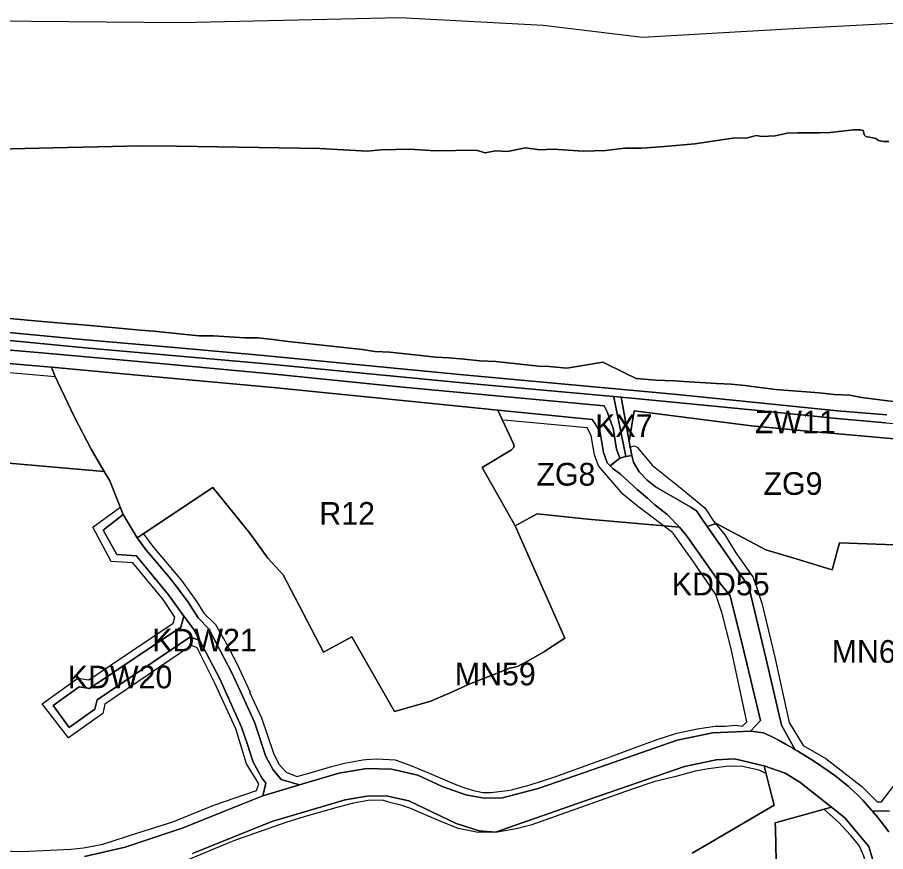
# Model space of a CAD drawing. Extents: x 7428841 to 7433518, y 5545054 to 5546840.
# Drawn here: x 7432847.6 to 7433230.3, y 5546084.6 to 5546452.4 of the extents above; entities that cross this region are included whole.
import ezdxf

# ---------------------------------------------------------------- set-up
doc = ezdxf.new("R2010")
doc.units = 0
for name, color, linetype in [('linie_rozgraniczajace', 7, 'Continuous'), ('linie_zabudowy_nieprzekraczalne', 7, 'Continuous'), ('oznaczenia_przeznaczen', 7, 'Continuous')]:
    doc.layers.add(name, color=color, linetype=linetype)

msp = doc.modelspace()

# ---------------------------------------------------------------- linework, layer by layer
at = {"layer": 'linie_rozgraniczajace'}
for points in [[(7432820.67, 5546451.02), (7432919.88, 5546450.2), (7433016.26, 5546452.41), (7433079.45, 5546449.02), (7433123.15, 5546443.63), (7433164.03, 5546445.99), (7433192.29, 5546447.64), (7433261.86, 5546451.37)], [(7432839.38, 5546394.28), (7432850.87, 5546394.57), (7432869.68, 5546395.04), (7432889.49, 5546395.53), (7432901.99, 5546395.84), (7432917.75, 5546395.6), (7432953.9, 5546395.05), (7432980.95, 5546394.64), (7433001.88, 5546393.38), (7433007.91, 5546394.05), (7433020.66, 5546394.36), (7433031.79, 5546393.58), (7433049.82, 5546393.92), (7433053.75, 5546392.67), (7433058.4, 5546393.58), (7433063.61, 5546393.29), (7433071.62, 5546394.84), (7433077.92, 5546394.01), (7433083.76, 5546394.25), (7433090.41, 5546393.83), (7433097.06, 5546393.42), (7433101.99, 5546393.58), (7433106.92, 5546393.75), (7433115.46, 5546394.81), (7433122.89, 5546394.68), (7433132.88, 5546395.52), (7433146.3, 5546396.65), (7433155.13, 5546397.98), (7433163.95, 5546399.31), (7433168.93, 5546399.15), (7433173.35, 5546400.34), (7433175.83, 5546399.86), (7433178.74, 5546400.05), (7433181.65, 5546400.24), (7433186.87, 5546401.39), (7433191.63, 5546401.44), (7433196.38, 5546401.49), (7433201.14, 5546401.54), (7433205.9, 5546401.58), (7433210.99, 5546402.19), (7433216.09, 5546402.79), (7433217.69, 5546402.78), (7433219.3, 5546402.78), (7433220.4, 5546402.49), (7433220.79, 5546401.54), (7433220.85, 5546400.55), (7433221.64, 5546399.87), (7433223.99, 5546399.38), (7433225.98, 5546398.96), (7433227.25, 5546398.19), (7433229.37, 5546397.75), (7433231.77, 5546397.67)], [(7433231.77, 5546397.67), (7433229.37, 5546397.75), (7433227.25, 5546398.19), (7433225.98, 5546398.96), (7433223.99, 5546399.38), (7433221.64, 5546399.87), (7433220.85, 5546400.55), (7433220.79, 5546401.54), (7433220.4, 5546402.49), (7433219.3, 5546402.78), (7433217.69, 5546402.78), (7433216.09, 5546402.79), (7433210.99, 5546402.19), (7433205.9, 5546401.58), (7433201.14, 5546401.54), (7433196.38, 5546401.49), (7433191.63, 5546401.44), (7433186.87, 5546401.39), (7433181.65, 5546400.24), (7433178.74, 5546400.05), (7433175.83, 5546399.86), (7433173.35, 5546400.34), (7433168.93, 5546399.15), (7433163.95, 5546399.31), (7433155.13, 5546397.98), (7433146.3, 5546396.65), (7433132.88, 5546395.52), (7433122.89, 5546394.68)], [(7433122.89, 5546394.68), (7433115.46, 5546394.81), (7433106.92, 5546393.75), (7433101.99, 5546393.58), (7433097.06, 5546393.42), (7433090.41, 5546393.83), (7433083.76, 5546394.25), (7433077.92, 5546394.01), (7433071.62, 5546394.84), (7433063.61, 5546393.29), (7433058.4, 5546393.58), (7433053.75, 5546392.67), (7433049.82, 5546393.92), (7433031.79, 5546393.58), (7433020.66, 5546394.36), (7433007.91, 5546394.05), (7433001.88, 5546393.38), (7432980.95, 5546394.64), (7432953.9, 5546395.05), (7432917.75, 5546395.6), (7432901.99, 5546395.84), (7432889.49, 5546395.53), (7432869.68, 5546395.04), (7432850.87, 5546394.57), (7432839.38, 5546394.28)], [(7432914.89, 5546313.38), (7432907.84, 5546314.09), (7432901.69, 5546314.57), (7432895.53, 5546315.05), (7432881.27, 5546316.48), (7432874.59, 5546317.01), (7432868.8, 5546317.51), (7432853.66, 5546318.81), (7432842.75, 5546319.75)], [(7432842.75, 5546319.75), (7432853.66, 5546318.81), (7432868.8, 5546317.51), (7432874.59, 5546317.01), (7432881.27, 5546316.48), (7432895.53, 5546315.05), (7432901.69, 5546314.57), (7432907.84, 5546314.09), (7432914.89, 5546313.38), (7432921.93, 5546312.66), (7432927.81, 5546312.07), (7432934.09, 5546312.05), (7432940.99, 5546311.6), (7432947.89, 5546311.16), (7432953.61, 5546311.13), (7432960.28, 5546310.34), (7432967.03, 5546309.58), (7432973.79, 5546308.83), (7432986.14, 5546307.48), (7432999.63, 5546305.92), (7433005.19, 5546305.15), (7433011.86, 5546304.77), (7433018.66, 5546304.05), (7433025.47, 5546303.34), (7433032.01, 5546302.61), (7433037.81, 5546302.29), (7433044.63, 5546301.65), (7433051.45, 5546301.01), (7433058.56, 5546300.64), (7433063.88, 5546300.13), (7433077.52, 5546298.69), (7433082.06, 5546298.54), (7433089.89, 5546297.8), (7433097.78, 5546299.07), (7433105.68, 5546300.35), (7433115.89, 5546295.37), (7433120.39, 5546293.13), (7433129.06, 5546292.49), (7433132.98, 5546292.36), (7433137.28, 5546292.11), (7433141.57, 5546291.86)], [(7433230.83, 5546277.11), (7433209.16, 5546279), (7433173.06, 5546282.65), (7433136.97, 5546286.3), (7433090.54, 5546290.56), (7433044.1, 5546294.82), (7433000.08, 5546299.08), (7432956.05, 5546303.33), (7432916.93, 5546306.79), (7432877.8, 5546310.25), (7432808.08, 5546316.9)], [(7432808.08, 5546316.9), (7432877.8, 5546310.25), (7432916.93, 5546306.79), (7432956.05, 5546303.33), (7433000.08, 5546299.08), (7433044.1, 5546294.82), (7433090.54, 5546290.56), (7433136.97, 5546286.3), (7433173.06, 5546282.65), (7433209.16, 5546279), (7433230.83, 5546277.11)], [(7432807.79, 5546313.42), (7432877.5, 5546306.77), (7432955.75, 5546299.84), (7432999.77, 5546295.59), (7433043.79, 5546291.34), (7433110.39, 5546285.23), (7433110.44, 5546285.12), (7433110.52, 5546284.96), (7433113.18, 5546271.96), (7433115.88, 5546258.74), (7433113.22, 5546258.1), (7433111.76, 5546262.08), (7433110.21, 5546271.36), (7433108.51, 5546275.97), (7433107.78, 5546278.2), (7433106.3, 5546281.18), (7433017.57, 5546289.41), (7432961.02, 5546295.15), (7432902.7, 5546300.48), (7432859.86, 5546304.41), (7432799.1, 5546309.67)], [(7433230.5, 5546273.63), (7433208.84, 5546275.52), (7433172.74, 5546279.17), (7433136.65, 5546282.81), (7433113.77, 5546284.91), (7433110.39, 5546285.23), (7433043.79, 5546291.34), (7432999.77, 5546295.59), (7432955.75, 5546299.84), (7432877.5, 5546306.77), (7432807.79, 5546313.42)], [(7433233.67, 5546283.05), (7433219.69, 5546284.79), (7433214.51, 5546285.82), (7433207.65, 5546286.2), (7433200.99, 5546286.81), (7433181.84, 5546288.37), (7433168.25, 5546290.14), (7433162.28, 5546290.71), (7433155.84, 5546291.02), (7433141.57, 5546291.86), (7433137.28, 5546292.11), (7433132.98, 5546292.36), (7433129.06, 5546292.49), (7433120.39, 5546293.13), (7433115.89, 5546295.37), (7433105.68, 5546300.35), (7433097.78, 5546299.07), (7433089.89, 5546297.8), (7433082.06, 5546298.54), (7433077.52, 5546298.69), (7433063.88, 5546300.13), (7433058.56, 5546300.64), (7433051.45, 5546301.01), (7433044.63, 5546301.65), (7433037.81, 5546302.29), (7433032.01, 5546302.61), (7433025.47, 5546303.34), (7433018.66, 5546304.05), (7433011.86, 5546304.77), (7433005.19, 5546305.15), (7432999.63, 5546305.92), (7432986.14, 5546307.48), (7432973.79, 5546308.83), (7432967.03, 5546309.58), (7432960.28, 5546310.34), (7432953.61, 5546311.13), (7432947.89, 5546311.16), (7432940.99, 5546311.6), (7432934.09, 5546312.05), (7432927.81, 5546312.07), (7432921.93, 5546312.66), (7432914.89, 5546313.38)], [(7432799.1, 5546309.67), (7432859.86, 5546304.41), (7432902.7, 5546300.48), (7432961.02, 5546295.15), (7433017.57, 5546289.41), (7433106.3, 5546281.18), (7433107.78, 5546278.2), (7433108.51, 5546275.97), (7433110.21, 5546271.36), (7433111.76, 5546262.08), (7433113.22, 5546258.1), (7433108.92, 5546254.68), (7433107.59, 5546256.03), (7433105.93, 5546260.53), (7433104.45, 5546269.39), (7433102.36, 5546273.27), (7433100.96, 5546275.11), (7433072.74, 5546277.92), (7433059.45, 5546279.24), (7433027.71, 5546282.4), (7432960.43, 5546289.18), (7432902.15, 5546294.5), (7432862.64, 5546298.13), (7432859.33, 5546298.44), (7432798.57, 5546303.7)], [(7432798.57, 5546303.7), (7432859.33, 5546298.44), (7432862.64, 5546298.13), (7432864.08, 5546294.4), (7432872.66, 5546276.5), (7432880.16, 5546261.97), (7432885.89, 5546252.22), (7432828.56, 5546257.26)], [(7433141.57, 5546291.86), (7433155.84, 5546291.02), (7433162.28, 5546290.71), (7433168.25, 5546290.14), (7433181.84, 5546288.37), (7433200.99, 5546286.81), (7433207.65, 5546286.2), (7433214.51, 5546285.82), (7433219.69, 5546284.79), (7433233.67, 5546283.05)], [(7432828.56, 5546257.26), (7432885.89, 5546252.22), (7432888.33, 5546248.05), (7432894.28, 5546233.3), (7432885.45, 5546226.26), (7432891.41, 5546215.6), (7432900.11, 5546215.02), (7432900.42, 5546214.53), (7432907.32, 5546206.2), (7432914.21, 5546197.88), (7432920.95, 5546188.39), (7432919.64, 5546183.63), (7432879.49, 5546156.55), (7432874.93, 5546157.22), (7432863.34, 5546149.04), (7432870.43, 5546139.37), (7432881.81, 5546147.39), (7432882.87, 5546151.6), (7432923.71, 5546179.14), (7432927.93, 5546177.85), (7432936.8, 5546160.85), (7432946.48, 5546139.51), (7432949.04, 5546131.79), (7432951.6, 5546124.06), (7432955.44, 5546117.21), (7432957.08, 5546114.82), (7432955.78, 5546109.25), (7432938.26, 5546102.18), (7432920.74, 5546095.1), (7432895.13, 5546086.53), (7432877.19, 5546082.5)], [(7433232.08, 5546102.4), (7433224.39, 5546102.64), (7433224.12, 5546102.95), (7433220.24, 5546107.28), (7433218.18, 5546109.35), (7433213.98, 5546113.28), (7433208.47, 5546117.78), (7433204.96, 5546120.21), (7433198.97, 5546124.29), (7433191.63, 5546128.84), (7433190.5, 5546129.51), (7433184.5, 5546140.33), (7433177.66, 5546169.43), (7433170.1, 5546201.33), (7433158.52, 5546218.09), (7433151.7, 5546227.97), (7433155.69, 5546229.21), (7433177.54, 5546217.71), (7433190.86, 5546213.73), (7433206.76, 5546208.86), (7433209.98, 5546220.72), (7433250.57, 5546219.26)], [(7432877.19, 5546082.5), (7432895.13, 5546086.53), (7432920.74, 5546095.1), (7432938.26, 5546102.18), (7432955.78, 5546109.25), (7432971.96, 5546114.03), (7432989.36, 5546119.17), (7433001.73, 5546121.3), (7433012.5, 5546120.97), (7433024.08, 5546118.38), (7433034.82, 5546113.27), (7433045.32, 5546109.72), (7433053.34, 5546108.19), (7433061.5, 5546108.26), (7433077.24, 5546112.43), (7433097.65, 5546119.55), (7433138.47, 5546133.8), (7433154.14, 5546137.04), (7433170.78, 5546137.72), (7433176.57, 5546137.01), (7433180.29, 5546135.17), (7433183.71, 5546133.44), (7433186.57, 5546131.81), (7433189.37, 5546130.18), (7433190.5, 5546129.51), (7433191.63, 5546128.84), (7433198.97, 5546124.29), (7433204.96, 5546120.21), (7433208.47, 5546117.78), (7433213.98, 5546113.28), (7433218.18, 5546109.35), (7433220.24, 5546107.28), (7433224.12, 5546102.95), (7433224.39, 5546102.64), (7433226.85, 5546099.7), (7433229.88, 5546095.77), (7433231.75, 5546093.31)], [(7433225.12, 5546079.37), (7433222.89, 5546086.94), (7433212.43, 5546099.54), (7433206.42, 5546104.28), (7433192.54, 5546115.22), (7433186.06, 5546119.23), (7433176.83, 5546122.38), (7433176.68, 5546122.43), (7433163.71, 5546125.46), (7433155.61, 5546125.09), (7433141.68, 5546122.21), (7433100.03, 5546107.67), (7433058.38, 5546093.14), (7433051.17, 5546093.74), (7433041.11, 5546096.99), (7433020.14, 5546106.96), (7433010.99, 5546109.01), (7433002.57, 5546109.27), (7432992.09, 5546107.46), (7432959.73, 5546097.91), (7432942.31, 5546090.87), (7432924.89, 5546083.84)], [(7432924.89, 5546083.84), (7432942.31, 5546090.87), (7432959.73, 5546097.91), (7432992.09, 5546107.46), (7433002.57, 5546109.27), (7433010.99, 5546109.01), (7433020.14, 5546106.96), (7433041.11, 5546096.99), (7433051.17, 5546093.74), (7433058.38, 5546093.14), (7433100.03, 5546107.67), (7433141.68, 5546122.21), (7433155.61, 5546125.09), (7433163.71, 5546125.46), (7433176.68, 5546122.43), (7433176.83, 5546122.38), (7433179.52, 5546111.81), (7433181.22, 5546105.13), (7433153.11, 5546088.58), (7433145.11, 5546083.9)], [(7433145.11, 5546083.9), (7433153.11, 5546088.58), (7433181.22, 5546105.13), (7433179.52, 5546111.81), (7433176.83, 5546122.38), (7433186.06, 5546119.23), (7433192.54, 5546115.22), (7433206.42, 5546104.28), (7433181.68, 5546097.34), (7433181.74, 5546094.87), (7433182.26, 5546073.37)], [(7433231.75, 5546093.31), (7433229.88, 5546095.77), (7433226.85, 5546099.7), (7433224.39, 5546102.64), (7433232.08, 5546102.4)]]:
    msp.add_lwpolyline(points, dxfattribs=at)
for points in [[(7432862.64, 5546298.13), (7432902.15, 5546294.5), (7432960.43, 5546289.18), (7433027.71, 5546282.4), (7433059.45, 5546279.24), (7433066.28, 5546264.45), (7433066.56, 5546263.05), (7433065.41, 5546261.8), (7433052.44, 5546253.98), (7433066.99, 5546228.22), (7433088.88, 5546178.79), (7433084.41, 5546175.85), (7433079.94, 5546172.91), (7433074.04, 5546169.53), (7433068.14, 5546166.16), (7433065.44, 5546165.63), (7433064.51, 5546165.45), (7433058.03, 5546162.9), (7433051.22, 5546160.22), (7433049.14, 5546159.37), (7433047.06, 5546158.52), (7433038.12, 5546154.54), (7433032.55, 5546152.09), (7433029.94, 5546150.98), (7433013.91, 5546146.39), (7432995.06, 5546179.32), (7432982.55, 5546172.6), (7432964.81, 5546206.61), (7432958.08, 5546213.94), (7432950.08, 5546225.06), (7432933.74, 5546245.1), (7432900.41, 5546222.88), (7432894.28, 5546233.3), (7432888.33, 5546248.05), (7432885.89, 5546252.22), (7432880.16, 5546261.97), (7432872.66, 5546276.5), (7432864.08, 5546294.4)], [(7433110.39, 5546285.23), (7433113.77, 5546284.91), (7433117.27, 5546265.37), (7433118.51, 5546259.28), (7433115.88, 5546258.74), (7433113.18, 5546271.96), (7433110.52, 5546284.96), (7433110.44, 5546285.12)], [(7433113.77, 5546284.91), (7433136.65, 5546282.81), (7433172.74, 5546279.17), (7433208.84, 5546275.52), (7433230.5, 5546273.63), (7433252.15, 5546271.73), (7433253.43, 5546271.58), (7433255.12, 5546269.63), (7433254.95, 5546265.01), (7433254.48, 5546260.79), (7433254.25, 5546258.49), (7433253.62, 5546251.37), (7433253.4, 5546249.53), (7433252.54, 5546245.99), (7433252.35, 5546250.6), (7433251.8, 5546264.94), (7433221.23, 5546267.73), (7433194.42, 5546270.18), (7433171.16, 5546272.36), (7433119.54, 5546278.87), (7433117.27, 5546265.37)], [(7433052.44, 5546253.98), (7433065.41, 5546261.8), (7433066.56, 5546263.05), (7433066.28, 5546264.45), (7433059.45, 5546279.24), (7433072.74, 5546277.92), (7433100.96, 5546275.11), (7433102.36, 5546273.27), (7433104.45, 5546269.39), (7433105.93, 5546260.53), (7433107.59, 5546256.03), (7433108.92, 5546254.68), (7433110.25, 5546253.33), (7433113.28, 5546251.24), (7433120.82, 5546244.22), (7433125.45, 5546240.42), (7433128.6, 5546237.55), (7433134.12, 5546233.29), (7433139.55, 5546227.71), (7433099.1, 5546231.11), (7433076.7, 5546233.49), (7433066.99, 5546228.22)], [(7433117.27, 5546265.37), (7433119.54, 5546278.87), (7433171.16, 5546272.36), (7433194.42, 5546270.18), (7433221.23, 5546267.73), (7433251.8, 5546264.94), (7433252.35, 5546250.6), (7433252.54, 5546245.99), (7433252.12, 5546239.8), (7433251.58, 5546232.64), (7433250.57, 5546219.26), (7433209.98, 5546220.72), (7433206.76, 5546208.86), (7433190.86, 5546213.73), (7433177.54, 5546217.71), (7433155.69, 5546229.21), (7433151.7, 5546227.97), (7433146.94, 5546234.85), (7433144.44, 5546236.45), (7433128.87, 5546245.38), (7433125.22, 5546248.37), (7433121.64, 5546252.01), (7433119.2, 5546256.34), (7433118.51, 5546259.28)], [(7433108.92, 5546254.68), (7433113.22, 5546258.1), (7433115.88, 5546258.74), (7433118.51, 5546259.28), (7433119.2, 5546256.34), (7433121.64, 5546252.01), (7433125.22, 5546248.37), (7433128.87, 5546245.38), (7433144.44, 5546236.45), (7433146.94, 5546234.85), (7433151.7, 5546227.97), (7433158.52, 5546218.09), (7433170.1, 5546201.33), (7433177.66, 5546169.43), (7433184.5, 5546140.33), (7433190.5, 5546129.51), (7433189.37, 5546130.18), (7433186.57, 5546131.81), (7433183.71, 5546133.44), (7433180.29, 5546135.17), (7433176.57, 5546137.01), (7433170.78, 5546137.72), (7433175.24, 5546142.49), (7433167.34, 5546174.89), (7433161.84, 5546197.45), (7433157.6, 5546202.6), (7433150.25, 5546213.09), (7433142.9, 5546223.58), (7433139.55, 5546227.71), (7433134.12, 5546233.29), (7433128.6, 5546237.55), (7433125.45, 5546240.42), (7433120.82, 5546244.22), (7433113.28, 5546251.24), (7433110.25, 5546253.33)], [(7432900.41, 5546222.88), (7432933.74, 5546245.1), (7432950.08, 5546225.06), (7432958.08, 5546213.94), (7432964.81, 5546206.61), (7432982.55, 5546172.6), (7432995.06, 5546179.32), (7433013.91, 5546146.39), (7433029.94, 5546150.98), (7433032.55, 5546152.09), (7433038.12, 5546154.54), (7433047.06, 5546158.52), (7433049.14, 5546159.37), (7433051.22, 5546160.22), (7433058.03, 5546162.9), (7433064.51, 5546165.45), (7433065.44, 5546165.63), (7433068.14, 5546166.16), (7433074.04, 5546169.53), (7433079.94, 5546172.91), (7433084.41, 5546175.85), (7433088.88, 5546178.79), (7433066.99, 5546228.22), (7433076.7, 5546233.49), (7433099.1, 5546231.11), (7433139.55, 5546227.71), (7433142.9, 5546223.58), (7433150.25, 5546213.09), (7433157.6, 5546202.6), (7433161.84, 5546197.45), (7433167.34, 5546174.89), (7433175.24, 5546142.49), (7433170.78, 5546137.72), (7433154.14, 5546137.04), (7433138.47, 5546133.8), (7433097.65, 5546119.55), (7433077.24, 5546112.43), (7433061.5, 5546108.26), (7433053.34, 5546108.19), (7433045.32, 5546109.72), (7433034.82, 5546113.27), (7433024.08, 5546118.38), (7433012.5, 5546120.97), (7433001.73, 5546121.3), (7432989.36, 5546119.17), (7432971.96, 5546114.03), (7432963.95, 5546116.39), (7432960.4, 5546120.63), (7432957.11, 5546126.49), (7432952.08, 5546141.7), (7432946.79, 5546153.36), (7432942.2, 5546163.48), (7432932.09, 5546182.85), (7432927.38, 5546187.65), (7432923.99, 5546193.01), (7432922.92, 5546194.52), (7432918.2, 5546200.9), (7432914.54, 5546205.62), (7432910.48, 5546210.41), (7432906.41, 5546215.2), (7432904.46, 5546217.49)], [(7432885.45, 5546226.26), (7432894.28, 5546233.3), (7432900.41, 5546222.88), (7432904.46, 5546217.49), (7432906.41, 5546215.2), (7432910.48, 5546210.41), (7432914.54, 5546205.62), (7432918.2, 5546200.9), (7432922.92, 5546194.52), (7432923.99, 5546193.01), (7432927.38, 5546187.65), (7432932.09, 5546182.85), (7432942.2, 5546163.48), (7432946.79, 5546153.36), (7432952.08, 5546141.7), (7432957.11, 5546126.49), (7432960.4, 5546120.63), (7432963.95, 5546116.39), (7432971.96, 5546114.03), (7432955.78, 5546109.25), (7432957.08, 5546114.82), (7432955.44, 5546117.21), (7432951.6, 5546124.06), (7432949.04, 5546131.79), (7432946.48, 5546139.51), (7432936.8, 5546160.85), (7432927.93, 5546177.85), (7432926.53, 5546180.38), (7432925.16, 5546183.05), (7432920.95, 5546188.39), (7432914.21, 5546197.88), (7432907.32, 5546206.2), (7432900.42, 5546214.53), (7432900.11, 5546215.02), (7432891.41, 5546215.6)], [(7432863.34, 5546149.04), (7432874.93, 5546157.22), (7432879.49, 5546156.55), (7432919.64, 5546183.63), (7432920.95, 5546188.39), (7432925.16, 5546183.05), (7432926.53, 5546180.38), (7432927.93, 5546177.85), (7432923.71, 5546179.14), (7432882.87, 5546151.6), (7432881.81, 5546147.39), (7432870.43, 5546139.37)], [(7433182.64, 5546045.32), (7433182.26, 5546073.37), (7433181.74, 5546094.87), (7433181.68, 5546097.34), (7433206.42, 5546104.28), (7433212.43, 5546099.54), (7433222.89, 5546086.94), (7433225.12, 5546079.37), (7433224.43, 5546066.7), (7433220.45, 5546053.25), (7433214.62, 5546040.35), (7433208.79, 5546031.51), (7433201.04, 5546029.2), (7433184.08, 5546045.29)]]:
    msp.add_lwpolyline(points, close=True, dxfattribs=at)
at = {"layer": 'linie_zabudowy_nieprzekraczalne'}
for points in [[(7432864.47, 5546293.93), (7432798.22, 5546299.71), (7432741.64, 5546304.74), (7432693.81, 5546309.57), (7432638.44, 5546315.28), (7432608.53, 5546318.33), (7432602.31, 5546318.9)], [(7433136.37, 5546225.28), (7433121.5, 5546236.41), (7433114.55, 5546242.26), (7433103.84, 5546254.65), (7433102.05, 5546259.51), (7433100.62, 5546268.08), (7433098.84, 5546271.38), (7433062.08, 5546274.86)], [(7433117.44, 5546262.88), (7433119.46, 5546263.58), (7433120.81, 5546262.89)], [(7433120.81, 5546262.89), (7433127.37, 5546255), (7433140.7, 5546244.48), (7433150.6, 5546236.2)], [(7432916.99, 5546187.93), (7432911.89, 5546195.77), (7432898.47, 5546211.98), (7432889.04, 5546212.47), (7432880.92, 5546227.62), (7432892.78, 5546236.32)], [(7433150.6, 5546236.2), (7433154.66, 5546230.1), (7433159.46, 5546224.23), (7433164.37, 5546216.3), (7433171.75, 5546205.82), (7433173.19, 5546202.17), (7433175.81, 5546194.11), (7433181.54, 5546170.37), (7433187.79, 5546141.52), (7433194, 5546131.45)], [(7432903.27, 5546224.72), (7432907.4, 5546219.1)], [(7433167.18, 5546139.92), (7433169.2, 5546141.89), (7433162.23, 5546174.02), (7433158.28, 5546189.63), (7433155.48, 5546197.92), (7433145.35, 5546212.79), (7433136.5, 5546225.09)], [(7432907.4, 5546219.1), (7432920.04, 5546204.07), (7432926.69, 5546194.74), (7432929.86, 5546189.75)], [(7432926.83, 5546174.47), (7432924.43, 5546175.43), (7432886.15, 5546149.63), (7432885.33, 5546145.48), (7432870.14, 5546134.82), (7432858.5, 5546149.84), (7432874.21, 5546161.04), (7432879.11, 5546160.39), (7432916.34, 5546185.29), (7432916.99, 5546187.93)], [(7432929.86, 5546189.75), (7432935.02, 5546184.79), (7432939.72, 5546176.5), (7432944.15, 5546167.78), (7432950.25, 5546154.93)], [(7433194, 5546131.45), (7433204.01, 5546125.67), (7433211.88, 5546119.54), (7433219.74, 5546113.4), (7433226.62, 5546106.5), (7433228.47, 5546106.54), (7433239.67, 5546121.13), (7433242.09, 5546124.41), (7433244.28, 5546127.35), (7433249.29, 5546136.27), (7433255.13, 5546147.38), (7433261.51, 5546159.11), (7433264.96, 5546165.82), (7433270.61, 5546175.32), (7433277.78, 5546186.95)], [(7432953.08, 5546111.58), (7432954.11, 5546114.44), (7432948.57, 5546123.32), (7432943.87, 5546138.7), (7432934.51, 5546159.14), (7432926.83, 5546174.47)], [(7432950.01, 5546154.96), (7432955.26, 5546143.53), (7432960.53, 5546128.01), (7432962.94, 5546123.24), (7432966.05, 5546119.63), (7432970.88, 5546117.78)], [(7432970.88, 5546117.78), (7432970.88, 5546117.78), (7432977.7, 5546119.57), (7432986.16, 5546122.1), (7432991.8, 5546123.57), (7432999.91, 5546125.05), (7433001.23, 5546125.17), (7433006.13, 5546125.51), (7433014.09, 5546125.11), (7433021.13, 5546122.52), (7433029.09, 5546119.13), (7433041.92, 5546113.71), (7433045.3, 5546112.53), (7433048.69, 5546111.54), (7433052.74, 5546110.71), (7433056.46, 5546110.69), (7433063.46, 5546111.52), (7433065.45, 5546111.84), (7433073.67, 5546114.1), (7433084.52, 5546117.64), (7433103.24, 5546124.34), (7433107.72, 5546126.01), (7433119.2, 5546130.22), (7433129.64, 5546134.01), (7433138.38, 5546136.8), (7433147.32, 5546138.77), (7433155.24, 5546139.95), (7433159.55, 5546139.97), (7433164.23, 5546140.31), (7433167.18, 5546139.92)], [(7432741.07, 5546127.1), (7432742.24, 5546125.1), (7432743.88, 5546122.64), (7432744.39, 5546121.18), (7432747.16, 5546119.09), (7432751.67, 5546116), (7432755.97, 5546113.19), (7432762.44, 5546108.94), (7432775.89, 5546102.76), (7432785.69, 5546098.13), (7432796.46, 5546093.57), (7432801.96, 5546091.82), (7432827.89, 5546086.18), (7432835.14, 5546085.07), (7432849.82, 5546084.73), (7432871.14, 5546085.67), (7432876.84, 5546086.3), (7432885.26, 5546087.91), (7432900.67, 5546092.84), (7432916.09, 5546097.76), (7432934.2, 5546105.02), (7432953.08, 5546111.58)], [(7433177.2, 5546119.23), (7433174.65, 5546120.51), (7433167.28, 5546122.09), (7433161.13, 5546122.3), (7433152.23, 5546121.08), (7433146.46, 5546120.11), (7433137.85, 5546117.77), (7433128.22, 5546115.38), (7433118.13, 5546112.02), (7433073.94, 5546096.33), (7433067.49, 5546094.71), (7433058.38, 5546093.11), (7433049.96, 5546093.22), (7433041.98, 5546094.81), (7433033.18, 5546098.29), (7433020.67, 5546103.76), (7433016.66, 5546105.05), (7433012.38, 5546106.16), (7433008.56, 5546107.28), (7433002.2, 5546107.17), (7432995.79, 5546106), (7432989.02, 5546104.21), (7432975.55, 5546100.44), (7432966.46, 5546097.54), (7432943.81, 5546089.6), (7432940.13, 5546088.26), (7432923.27, 5546081.18)], [(7433206.67, 5546035.14), (7433209.68, 5546039.7), (7433215.97, 5546052.31), (7433219.17, 5546060.17), (7433222.04, 5546070.56), (7433221.79, 5546078.88), (7433220.67, 5546082.57), (7433218.66, 5546087.35), (7433214.86, 5546091.94), (7433209.62, 5546097.67), (7433203.08, 5546103.37)]]:
    msp.add_lwpolyline(points, dxfattribs=at)

# ---------------------------------------------------------------- texts
at = {"layer": 'oznaczenia_przeznaczen'}
for s, p in [('KX7', (7433102.32, 5546267.46)), ('ZW11', (7433172.72, 5546269.03)), ('ZG8', (7433076.4, 5546245.98)), ('ZG9', (7433176.5, 5546241.9)), ('R12', (7432980.72, 5546228.72)), ('KDD55', (7433136.1, 5546197.6)), ('KDW21', (7432907.08, 5546172.85)), ('MN60', (7433206.57, 5546167.88)), ('KDW20', (7432869.87, 5546156.61)), ('MN59', (7433040.44, 5546157.9))]:
    msp.add_text(s, height=10, dxfattribs=at).set_placement(p)

doc.saveas('drawing.dxf')
